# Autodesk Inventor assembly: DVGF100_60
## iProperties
Created: 2010-04
Part Number: DVGF100_60
Document SubType Name: Assembly
Designer: TB
Mass: 3254.64 g
Surface Area: 3351.76 cm^2
Volume: 3254.64 cm^3
Density: 1 g/cm^3
Description: KM DVGF 100/60 - 100 mm
Slaglengde: 100.000 mm
Author: TB
